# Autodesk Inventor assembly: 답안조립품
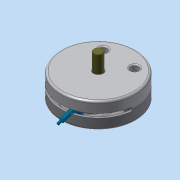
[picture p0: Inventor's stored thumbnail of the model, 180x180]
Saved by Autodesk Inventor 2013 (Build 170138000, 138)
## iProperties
Created: 2015-04
Part Number: 답안조립품
Document SubType Name: Assembly
Designer: Administrator
Author: Administrator
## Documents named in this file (10)
- C:\Users\Administrator\Desktop\450406V1013\답안조립품.iam
- C:\Users\Administrator\Desktop\450406V1013\본체.ipt
- C:\Users\Administrator\Desktop\450406V1013\M 10 x 35.ipt
- C:\Users\Administrator\Desktop\450406V1013\덮개.ipt
- C:\Users\Administrator\Desktop\450406V1013\멈춤링.ipt
- C:\Users\Administrator\Desktop\450406V1013\베어링62_22.ipt
- C:\Users\Administrator\Desktop\450406V1013\슬라이더.ipt
- C:\Users\Administrator\Desktop\450406V1013\슬라이더2.ipt
- C:\Users\Administrator\Desktop\450406V1013\축.ipt
- C:\Users\Administrator\Desktop\450406V1013\평행핀.ipt
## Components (2 placed, 1 different names)
1. M 10 x 35:1
2. M 10 x 35:2
